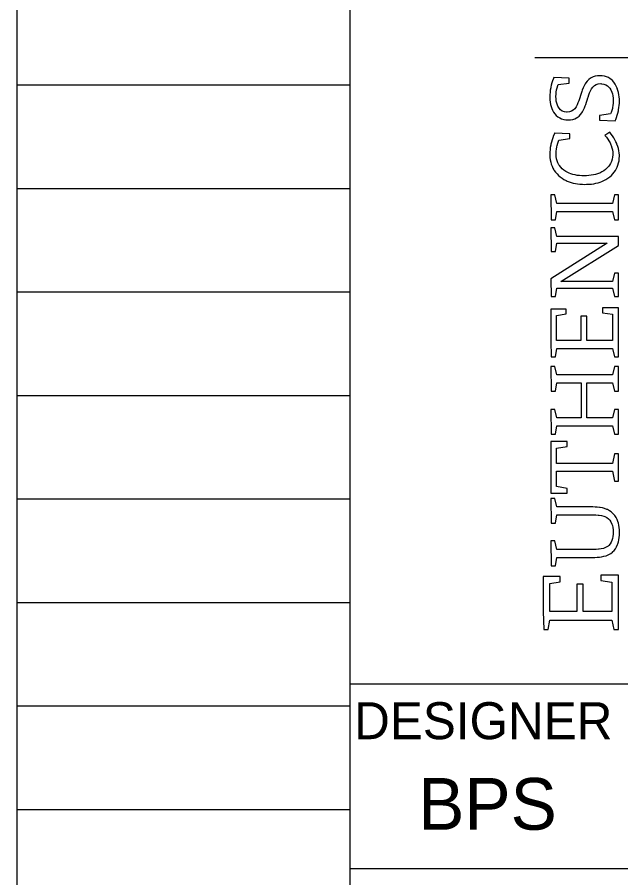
# Model space of a CAD drawing. Extents: x 0 to 34, y 0 to 22.
# Drawn here: x 31.1 to 32.732, y 2.475 to 4.803 of the extents above; entities that cross this region are included whole.
import ezdxf

# ---------------------------------------------------------------- set-up
doc = ezdxf.new("R2010")
doc.units = 0
for name, color, linetype in [('SH_Border', 7, 'Continuous'), ('SH_Data', 7, 'Continuous'), ('SH_Logo', 7, 'Continuous')]:
    doc.layers.add(name, color=color, linetype=linetype)

msp = doc.modelspace()

# ---------------------------------------------------------------- linework, layer by layer
at = {"layer": 'SH_Border'}
for p, q in [((32, 0.5), (32, 21.5)), ((32, 3), (33.5, 3)), ((32, 2.5), (33.5, 2.5))]:
    msp.add_line(p, q, dxfattribs=at)
at = {"layer": 'SH_Data'}
for p, q in [((31.1, 0.98), (31.1, 21.14)), ((32, 0.98), (32, 21.14)), ((31.1, 4.62), (32, 4.62)), ((31.1, 4.34), (32, 4.34)), ((31.1, 4.06), (32, 4.06)), ((31.1, 3.78), (32, 3.78)), ((31.1, 3.5), (32, 3.5)), ((31.1, 3.22), (32, 3.22)), ((31.1, 2.94), (32, 2.94)), ((31.1, 2.66), (32, 2.66))]:
    msp.add_line(p, q, dxfattribs=at)
at = {"layer": 'SH_Logo'}
msp.add_line((32.4993, 4.6945), (32.8389, 4.6945), dxfattribs=at)
for points in [[(32.6075, 4.5559), (32.6035, 4.5518), (32.5991, 4.549), (32.5936, 4.5472), (32.5862, 4.5465), (32.5794, 4.5474), (32.5739, 4.5495), (32.5692, 4.5527), (32.5651, 4.5572), (32.562, 4.5623), (32.5596, 4.5681), (32.5589, 4.5705), (32.5577, 4.5764), (32.5569, 4.5824), (32.5567, 4.5887), (32.5569, 4.5949), (32.5575, 4.6009), (32.5585, 4.607), (32.5599, 4.6127), (32.5616, 4.6186), (32.5627, 4.6212), (32.5922, 4.6249), (32.5922, 4.638), (32.5509, 4.6402), (32.5497, 4.6372), (32.5475, 4.6314), (32.5456, 4.6256), (32.5441, 4.6198), (32.5428, 4.6139), (32.5425, 4.6123), (32.5414, 4.606), (32.5407, 4.6), (32.5403, 4.5939), (32.5401, 4.5881), (32.5401, 4.5859), (32.5405, 4.5795), (32.5412, 4.5734), (32.5423, 4.5674), (32.5437, 4.5617), (32.5456, 4.5563), (32.5474, 4.5521), (32.5504, 4.5467), (32.5539, 4.5417), (32.5577, 4.5375), (32.5622, 4.5338), (32.5668, 4.5307), (32.572, 4.5284), (32.5777, 4.5267), (32.5838, 4.5256), (32.5903, 4.5253), (32.5962, 4.5256), (32.6023, 4.5266), (32.6078, 4.5284), (32.6127, 4.5308), (32.6145, 4.5319), (32.6193, 4.5356), (32.6235, 4.5399), (32.6271, 4.5448), (32.6286, 4.5472), (32.6314, 4.5525), (32.634, 4.5581), (32.6361, 4.5639), (32.6373, 4.5675), (32.6393, 4.5734), (32.6411, 4.5791), (32.6429, 4.585), (32.6436, 4.5873), (32.6457, 4.5932), (32.6479, 4.5988), (32.6503, 4.6041), (32.6531, 4.6093), (32.6567, 4.6142), (32.6608, 4.6183), (32.6609, 4.6184), (32.6657, 4.6213), (32.6713, 4.623), (32.6779, 4.6236), (32.6802, 4.6235), (32.6864, 4.6225), (32.6918, 4.6205), (32.6965, 4.6173), (32.6981, 4.6158), (32.7021, 4.6115), (32.7053, 4.6065), (32.7078, 4.6007), (32.7093, 4.5963), (32.7107, 4.5905), (32.7115, 4.5844), (32.7118, 4.5775), (32.7115, 4.5709), (32.7108, 4.5648), (32.7097, 4.5587), (32.7093, 4.5568), (32.7077, 4.5509), (32.7057, 4.5451), (32.7043, 4.5417), (32.6742, 4.5376), (32.6742, 4.5248), (32.7173, 4.5232), (32.7187, 4.5266), (32.7208, 4.5324), (32.7226, 4.5382), (32.7242, 4.5441), (32.7255, 4.55), (32.726, 4.5527), (32.7271, 4.5588), (32.7277, 4.5648), (32.7282, 4.5708), (32.7283, 4.5768), (32.7283, 4.5812), (32.7278, 4.5875), (32.7271, 4.5936), (32.7259, 4.5994), (32.7244, 4.6052), (32.7223, 4.6114), (32.7199, 4.6171), (32.7169, 4.6224), (32.7135, 4.6273), (32.7096, 4.6317), (32.7052, 4.6357), (32.7036, 4.6369), (32.6988, 4.6398), (32.6935, 4.642), (32.6878, 4.6436), (32.6816, 4.6446), (32.675, 4.6449), (32.6688, 4.6446), (32.6626, 4.6436), (32.6571, 4.6419), (32.6521, 4.6396), (32.6501, 4.6383), (32.6453, 4.6345), (32.641, 4.6303), (32.6374, 4.6254), (32.6358, 4.6228), (32.6329, 4.6176), (32.6303, 4.612), (32.628, 4.6063), (32.6267, 4.6026), (32.6229, 4.5911), (32.6211, 4.5852), (32.6184, 4.577), (32.6161, 4.5714), (32.6137, 4.5661), (32.611, 4.5608)], [(32.6742, 4.5376), (32.6742, 4.5248), (32.7173, 4.5232), (32.7187, 4.5266), (32.7208, 4.5324), (32.7226, 4.5382), (32.7242, 4.5441), (32.7255, 4.55), (32.726, 4.5527), (32.7271, 4.5588), (32.7277, 4.5648), (32.7282, 4.5708), (32.7283, 4.5768), (32.7283, 4.5812), (32.7278, 4.5875), (32.7271, 4.5936), (32.7259, 4.5994), (32.7244, 4.6052), (32.7226, 4.6107), (32.7223, 4.6114), (32.7199, 4.6171), (32.7169, 4.6224), (32.7135, 4.6273), (32.7096, 4.6317), (32.7052, 4.6357), (32.7036, 4.6369), (32.6988, 4.6398), (32.6935, 4.642), (32.6878, 4.6436), (32.6816, 4.6446), (32.675, 4.6449), (32.6688, 4.6446), (32.6626, 4.6436), (32.6571, 4.6419), (32.6521, 4.6396), (32.6501, 4.6383), (32.6453, 4.6345), (32.641, 4.6303), (32.6374, 4.6254), (32.6358, 4.6228), (32.6329, 4.6176), (32.6303, 4.612), (32.628, 4.6063), (32.6267, 4.6026), (32.6248, 4.5968), (32.6229, 4.5911), (32.6211, 4.5852), (32.6204, 4.5829), (32.6184, 4.577), (32.6161, 4.5714), (32.6137, 4.5661), (32.611, 4.5608), (32.6075, 4.5559), (32.6035, 4.5518), (32.5991, 4.549), (32.5936, 4.5472), (32.5871, 4.5466), (32.5856, 4.5466), (32.5794, 4.5474), (32.5739, 4.5495), (32.5693, 4.5526), (32.569, 4.5529), (32.5651, 4.5572), (32.562, 4.5623), (32.5596, 4.5681), (32.5589, 4.5705), (32.5577, 4.5764), (32.5569, 4.5824), (32.5567, 4.5886), (32.5567, 4.5889), (32.5569, 4.5949), (32.5575, 4.6009), (32.5585, 4.607), (32.5599, 4.6127), (32.5616, 4.6186), (32.5627, 4.6212), (32.5922, 4.6249), (32.5922, 4.638), (32.5509, 4.6402), (32.5497, 4.6372), (32.5475, 4.6314), (32.5456, 4.6256), (32.5441, 4.6198), (32.5428, 4.6139), (32.5425, 4.6123), (32.5414, 4.606), (32.5407, 4.6), (32.5403, 4.5939), (32.5401, 4.5881), (32.5401, 4.5859), (32.5405, 4.5795), (32.5412, 4.5734), (32.5423, 4.5674), (32.5437, 4.5617), (32.5456, 4.5563), (32.5474, 4.5521), (32.5504, 4.5467), (32.5539, 4.5417), (32.5577, 4.5375), (32.5622, 4.5338), (32.5668, 4.5307), (32.572, 4.5284), (32.5777, 4.5267), (32.5838, 4.5256), (32.5903, 4.5253), (32.5962, 4.5256), (32.6023, 4.5266), (32.6078, 4.5284), (32.6127, 4.5308), (32.6145, 4.5319), (32.6193, 4.5356), (32.6235, 4.5399), (32.6271, 4.5448), (32.6286, 4.5472), (32.6314, 4.5525), (32.634, 4.5581), (32.6361, 4.5639), (32.6373, 4.5675), (32.6393, 4.5734), (32.6411, 4.5791), (32.6429, 4.585), (32.6436, 4.5873), (32.6457, 4.5932), (32.6479, 4.5988), (32.6503, 4.6041), (32.6531, 4.6093), (32.6567, 4.6142), (32.6608, 4.6183), (32.6609, 4.6184), (32.6657, 4.6213), (32.6713, 4.623), (32.6779, 4.6236), (32.6802, 4.6235), (32.6864, 4.6225), (32.6918, 4.6205), (32.6965, 4.6173), (32.6981, 4.6158), (32.7021, 4.6115), (32.7053, 4.6065), (32.7078, 4.6007), (32.7093, 4.5963), (32.7107, 4.5905), (32.7115, 4.5844), (32.7118, 4.5781), (32.7118, 4.5768), (32.7115, 4.5709), (32.7108, 4.5648), (32.7097, 4.5587), (32.7093, 4.5568), (32.7077, 4.5509), (32.7057, 4.5451), (32.7043, 4.5417)], [(32.5558, 4.3837), (32.5596, 4.3793), (32.5637, 4.3751), (32.5682, 4.3712), (32.5731, 4.3676), (32.5784, 4.3644), (32.584, 4.3614), (32.5873, 4.3599), (32.5925, 4.3578), (32.5979, 4.3561), (32.6035, 4.3546), (32.6093, 4.3533), (32.6154, 4.3523), (32.6217, 4.3517), (32.6283, 4.3513), (32.635, 4.3511), (32.6396, 4.3512), (32.6463, 4.3515), (32.6527, 4.3521), (32.6589, 4.353), (32.6648, 4.3541), (32.6705, 4.3555), (32.6759, 4.3572), (32.6811, 4.3591), (32.686, 4.3614), (32.6861, 4.3614), (32.6918, 4.3644), (32.6971, 4.3677), (32.7021, 4.3713), (32.7065, 4.3752), (32.7106, 4.3794), (32.7143, 4.3839), (32.7176, 4.3887), (32.7197, 4.3923), (32.7223, 4.3977), (32.7245, 4.4033), (32.7261, 4.409), (32.7274, 4.4148), (32.7281, 4.4208), (32.7283, 4.4271), (32.7283, 4.4302), (32.7278, 4.436), (32.727, 4.442), (32.7257, 4.4479), (32.7239, 4.4539), (32.7218, 4.4599), (32.7212, 4.4613), (32.7189, 4.4666), (32.7163, 4.4719), (32.7133, 4.4771), (32.7099, 4.4822), (32.7062, 4.4872), (32.7021, 4.4922), (32.6892, 4.4835), (32.6932, 4.4787), (32.6969, 4.4736), (32.7001, 4.4685), (32.7029, 4.4633), (32.7052, 4.4581), (32.7059, 4.4562), (32.7079, 4.45), (32.7093, 4.4441), (32.7102, 4.4382), (32.7105, 4.4326), (32.7104, 4.431), (32.71, 4.4249), (32.7088, 4.419), (32.7069, 4.4134), (32.7044, 4.408), (32.7013, 4.4029), (32.6991, 4.3998), (32.6953, 4.3955), (32.691, 4.3916), (32.6862, 4.388), (32.6808, 4.3847), (32.675, 4.3818), (32.6741, 4.3815), (32.6691, 4.3796), (32.6637, 4.378), (32.658, 4.3766), (32.6521, 4.3756), (32.6458, 4.3748), (32.6393, 4.3744), (32.6324, 4.3742), (32.627, 4.3743), (32.6205, 4.3748), (32.6143, 4.3755), (32.6083, 4.3765), (32.6026, 4.3779), (32.5972, 4.3796), (32.5922, 4.3816), (32.589, 4.3831), (32.5834, 4.386), (32.5783, 4.3894), (32.5738, 4.3932), (32.5697, 4.3973), (32.5662, 4.4018), (32.5646, 4.4042), (32.562, 4.4093), (32.5599, 4.4147), (32.5584, 4.4205), (32.5575, 4.4267), (32.5572, 4.4331), (32.5572, 4.4347), (32.5575, 4.4406), (32.5582, 4.4467), (32.5593, 4.453), (32.5602, 4.4567), (32.5618, 4.4625), (32.5638, 4.4682), (32.5647, 4.4705), (32.5945, 4.4749), (32.5945, 4.4878), (32.5532, 4.4896), (32.553, 4.489), (32.5505, 4.4831), (32.5482, 4.4772), (32.5463, 4.4714), (32.5447, 4.4657), (32.5433, 4.4602), (32.5426, 4.4569), (32.5415, 4.4508), (32.5407, 4.4447), (32.5403, 4.4387), (32.5401, 4.4328), (32.5402, 4.4299), (32.5406, 4.4236), (32.5413, 4.4175), (32.5425, 4.4116), (32.5441, 4.4059), (32.5462, 4.4003), (32.5486, 4.3951), (32.5514, 4.39), (32.5523, 4.3885)], [(32.6205, 4.3748), (32.6143, 4.3755), (32.6083, 4.3765), (32.6026, 4.3779), (32.5972, 4.3796), (32.5922, 4.3816), (32.589, 4.3831), (32.5834, 4.386), (32.5783, 4.3894), (32.5738, 4.3932), (32.5697, 4.3973), (32.5662, 4.4018), (32.5646, 4.4042), (32.562, 4.4093), (32.5599, 4.4147), (32.5584, 4.4205), (32.5575, 4.4267), (32.5572, 4.4331), (32.5572, 4.4347), (32.5575, 4.4406), (32.5582, 4.4467), (32.5593, 4.453), (32.5602, 4.4567), (32.5618, 4.4625), (32.5638, 4.4682), (32.5647, 4.4705), (32.5945, 4.4749), (32.5945, 4.4878), (32.5533, 4.4896), (32.5505, 4.4831), (32.5482, 4.4772), (32.5463, 4.4714), (32.5447, 4.4657), (32.5433, 4.4602), (32.5426, 4.4569), (32.5415, 4.4508), (32.5407, 4.4447), (32.5403, 4.4387), (32.5401, 4.4328), (32.5402, 4.4299), (32.5406, 4.4236), (32.5413, 4.4175), (32.5425, 4.4116), (32.5441, 4.4059), (32.5462, 4.4003), (32.5486, 4.3951), (32.5514, 4.39), (32.5523, 4.3885), (32.5558, 4.3837), (32.5596, 4.3793), (32.5637, 4.3751), (32.5682, 4.3712), (32.5731, 4.3676), (32.5784, 4.3644), (32.584, 4.3614), (32.5873, 4.3599), (32.5925, 4.3578), (32.5979, 4.3561), (32.6035, 4.3546), (32.6093, 4.3533), (32.6154, 4.3523), (32.6217, 4.3517), (32.6283, 4.3513), (32.635, 4.3511), (32.6396, 4.3512), (32.6463, 4.3515), (32.6527, 4.3521), (32.6589, 4.353), (32.6648, 4.3541), (32.6705, 4.3555), (32.6759, 4.3572), (32.6811, 4.3591), (32.6866, 4.3617), (32.6918, 4.3644), (32.6971, 4.3677), (32.7021, 4.3713), (32.7065, 4.3752), (32.7106, 4.3794), (32.7143, 4.3839), (32.7176, 4.3887), (32.7197, 4.3923), (32.7223, 4.3977), (32.7245, 4.4033), (32.7261, 4.409), (32.7274, 4.4148), (32.7281, 4.4208), (32.7283, 4.4271), (32.7283, 4.4302), (32.7278, 4.436), (32.727, 4.442), (32.7257, 4.4479), (32.7239, 4.4539), (32.7218, 4.4599), (32.7212, 4.4613), (32.7189, 4.4666), (32.7163, 4.4719), (32.7133, 4.4771), (32.7099, 4.4822), (32.7062, 4.4872), (32.7021, 4.4922), (32.6892, 4.4835), (32.6932, 4.4787), (32.6969, 4.4736), (32.7001, 4.4685), (32.7029, 4.4633), (32.7052, 4.4581), (32.7059, 4.4562), (32.7079, 4.45), (32.7093, 4.4441), (32.7102, 4.4382), (32.7105, 4.4326), (32.7104, 4.431), (32.71, 4.4249), (32.7088, 4.419), (32.7069, 4.4134), (32.7044, 4.408), (32.7013, 4.4029), (32.6991, 4.3998), (32.6953, 4.3955), (32.691, 4.3916), (32.6862, 4.388), (32.6808, 4.3847), (32.6747, 4.3817), (32.6691, 4.3796), (32.6637, 4.378), (32.658, 4.3766), (32.6521, 4.3756), (32.6458, 4.3748), (32.6393, 4.3744), (32.6324, 4.3742), (32.627, 4.3743)], [(32.5425, 4.3225), (32.5438, 4.2554), (32.5551, 4.2554), (32.5592, 4.2781), (32.71, 4.2781), (32.7147, 4.2554), (32.726, 4.2554), (32.726, 4.3225), (32.7147, 4.3225), (32.71, 4.2996), (32.5589, 4.2996), (32.5538, 4.3225)], [(32.5589, 4.2996), (32.5538, 4.3225), (32.5425, 4.3225), (32.5438, 4.2554), (32.5551, 4.2554), (32.5592, 4.2781), (32.71, 4.2781), (32.7147, 4.2554), (32.726, 4.2554), (32.726, 4.3225), (32.7147, 4.3225), (32.71, 4.2996)], [(32.5591, 4.07), (32.71, 4.07), (32.7147, 4.0474), (32.726, 4.0474), (32.726, 4.111), (32.7147, 4.111), (32.71, 4.0884), (32.5703, 4.0884), (32.726, 4.1861), (32.726, 4.2103), (32.559, 4.2103), (32.5538, 4.2332), (32.5425, 4.2332), (32.5438, 4.1693), (32.5551, 4.1693), (32.5589, 4.1921), (32.6954, 4.1921), (32.5425, 4.0958), (32.5438, 4.0474), (32.5551, 4.0474)], [(32.5703, 4.0884), (32.726, 4.1861), (32.726, 4.2103), (32.559, 4.2103), (32.5538, 4.2332), (32.5425, 4.2332), (32.5438, 4.1693), (32.5551, 4.1693), (32.5589, 4.1921), (32.6954, 4.1921), (32.5425, 4.0958), (32.5438, 4.0474), (32.5551, 4.0474), (32.5591, 4.07), (32.71, 4.07), (32.7147, 4.0474), (32.726, 4.0474), (32.726, 4.111), (32.7147, 4.111), (32.71, 4.0884)], [(32.6829, 4.0169), (32.6829, 4.0038), (32.71, 3.9996), (32.71, 3.9283), (32.64, 3.9283), (32.64, 3.9946), (32.6242, 3.9946), (32.6242, 3.9283), (32.5585, 3.9283), (32.5585, 3.9964), (32.584, 4.0006), (32.584, 4.0138), (32.5425, 4.0138), (32.5425, 3.9281), (32.5438, 3.8843), (32.5551, 3.8843), (32.5592, 3.9068), (32.7099, 3.9068), (32.7147, 3.8843), (32.726, 3.8843), (32.726, 4.0169)], [(32.6242, 3.9946), (32.6242, 3.9283), (32.5585, 3.9283), (32.5585, 3.9964), (32.584, 4.0006), (32.584, 4.0138), (32.5425, 4.0138), (32.5425, 3.9281), (32.5438, 3.8843), (32.5551, 3.8843), (32.5592, 3.9068), (32.7099, 3.9068), (32.7147, 3.8843), (32.726, 3.8843), (32.726, 4.0169), (32.6829, 4.0169), (32.6829, 4.0038), (32.71, 3.9996), (32.71, 3.9283), (32.64, 3.9283), (32.64, 3.9946)], [(32.5425, 3.8587), (32.5438, 3.7918), (32.5551, 3.7918), (32.5591, 3.8143), (32.6245, 3.8143), (32.6245, 3.7193), (32.559, 3.7193), (32.5538, 3.7421), (32.5425, 3.7421), (32.5438, 3.6751), (32.5551, 3.6751), (32.5591, 3.6977), (32.7099, 3.6977), (32.7147, 3.6751), (32.726, 3.6751), (32.726, 3.7421), (32.7147, 3.7421), (32.7099, 3.7193), (32.6406, 3.7193), (32.6406, 3.8143), (32.7099, 3.8143), (32.7147, 3.7918), (32.726, 3.7918), (32.726, 3.8587), (32.7147, 3.8587), (32.7099, 3.8359), (32.559, 3.8359), (32.5538, 3.8587)], [(32.559, 3.8359), (32.5538, 3.8587), (32.5425, 3.8587), (32.5438, 3.7918), (32.5551, 3.7918), (32.5591, 3.8143), (32.6245, 3.8143), (32.6245, 3.7193), (32.559, 3.7193), (32.5538, 3.7421), (32.5425, 3.7421), (32.5438, 3.6751), (32.5551, 3.6751), (32.5591, 3.6977), (32.7099, 3.6977), (32.7147, 3.6751), (32.726, 3.6751), (32.726, 3.7421), (32.7147, 3.7421), (32.7099, 3.7193), (32.6406, 3.7193), (32.6406, 3.8143), (32.7099, 3.8143), (32.7147, 3.7918), (32.726, 3.7918), (32.726, 3.8587), (32.7147, 3.8587), (32.7099, 3.8359)], [(32.5585, 3.596), (32.5585, 3.6373), (32.5874, 3.642), (32.5874, 3.6551), (32.5425, 3.6551), (32.5425, 3.5156), (32.5874, 3.5156), (32.5874, 3.5287), (32.5585, 3.5333), (32.5585, 3.5747), (32.7099, 3.5747), (32.7147, 3.5484), (32.726, 3.5484), (32.726, 3.6223), (32.7147, 3.6223), (32.7099, 3.596)], [(32.5585, 3.596), (32.5585, 3.6373), (32.5874, 3.642), (32.5874, 3.6551), (32.5425, 3.6551), (32.5425, 3.5156), (32.5874, 3.5156), (32.5874, 3.5287), (32.5585, 3.5333), (32.5585, 3.5747), (32.7099, 3.5747), (32.7147, 3.5484), (32.726, 3.5484), (32.726, 3.6223), (32.7147, 3.6223), (32.7099, 3.596)], [(32.7116, 3.4095), (32.7114, 3.4048), (32.7108, 3.3983), (32.7097, 3.3926), (32.7081, 3.3877), (32.7063, 3.3834), (32.7032, 3.3782), (32.6994, 3.374), (32.6979, 3.3726), (32.6929, 3.3692), (32.6873, 3.3669), (32.6851, 3.3662), (32.6793, 3.3648), (32.6732, 3.3641), (32.6717, 3.3639), (32.6654, 3.3636), (32.6595, 3.3635), (32.5589, 3.3635), (32.5538, 3.3863), (32.5425, 3.3863), (32.5438, 3.3194), (32.5551, 3.3194), (32.559, 3.3419), (32.6595, 3.3419), (32.6619, 3.342), (32.6678, 3.3422), (32.6745, 3.3428), (32.6803, 3.3435), (32.6862, 3.3448), (32.6923, 3.3464), (32.6944, 3.3471), (32.6998, 3.3495), (32.705, 3.3526), (32.71, 3.3564), (32.71, 3.3565), (32.714, 3.3604), (32.7176, 3.365), (32.7207, 3.3703), (32.7233, 3.3764), (32.7242, 3.3787), (32.7257, 3.3839), (32.7268, 3.3895), (32.7277, 3.3956), (32.7282, 3.4022), (32.7283, 3.4092), (32.7283, 3.4095), (32.7282, 3.4163), (32.7277, 3.4227), (32.7268, 3.4287), (32.7256, 3.4343), (32.7242, 3.4394), (32.7223, 3.4443), (32.7195, 3.4499), (32.7163, 3.4548), (32.7125, 3.4591), (32.7109, 3.4607), (32.7063, 3.4648), (32.7013, 3.4682), (32.696, 3.471), (32.6941, 3.4718), (32.6884, 3.4739), (32.6826, 3.4755), (32.6766, 3.4768), (32.6748, 3.477), (32.6686, 3.4777), (32.6625, 3.4781), (32.6566, 3.4783), (32.5589, 3.4783), (32.5538, 3.5012), (32.5425, 3.5012), (32.5438, 3.4342), (32.5551, 3.4342), (32.5589, 3.4568), (32.6566, 3.4568), (32.6588, 3.4568), (32.6649, 3.4566), (32.671, 3.4562), (32.6739, 3.456), (32.6799, 3.4549), (32.6858, 3.4534), (32.6886, 3.4523), (32.694, 3.4496), (32.6989, 3.446), (32.702, 3.4428), (32.7053, 3.4378), (32.7081, 3.4321), (32.7093, 3.4282), (32.7106, 3.4226), (32.7112, 3.4163)], [(32.5589, 3.3635), (32.5538, 3.3863), (32.5425, 3.3863), (32.5438, 3.3194), (32.5551, 3.3194), (32.559, 3.3419), (32.6595, 3.3419), (32.6619, 3.342), (32.6678, 3.3422), (32.6745, 3.3428), (32.6803, 3.3435), (32.6862, 3.3448), (32.6923, 3.3464), (32.6944, 3.3471), (32.6998, 3.3495), (32.705, 3.3526), (32.71, 3.3564), (32.714, 3.3604), (32.7176, 3.365), (32.7207, 3.3703), (32.7233, 3.3764), (32.7242, 3.3787), (32.7257, 3.3839), (32.7268, 3.3895), (32.7277, 3.3956), (32.7282, 3.4022), (32.7283, 3.4092), (32.7283, 3.4095), (32.7282, 3.4163), (32.7277, 3.4227), (32.7268, 3.4287), (32.7256, 3.4343), (32.7242, 3.4394), (32.7223, 3.4443), (32.7195, 3.4499), (32.7163, 3.4548), (32.7125, 3.4591), (32.7109, 3.4607), (32.7063, 3.4648), (32.7013, 3.4682), (32.696, 3.471), (32.6941, 3.4718), (32.6884, 3.4739), (32.6826, 3.4755), (32.6766, 3.4768), (32.6748, 3.477), (32.6686, 3.4777), (32.6625, 3.4781), (32.6566, 3.4783), (32.5589, 3.4783), (32.5538, 3.5012), (32.5425, 3.5012), (32.5438, 3.4342), (32.5551, 3.4342), (32.5589, 3.4568), (32.6588, 3.4568), (32.6649, 3.4566), (32.671, 3.4562), (32.6739, 3.456), (32.6799, 3.4549), (32.6858, 3.4534), (32.6886, 3.4523), (32.694, 3.4496), (32.6989, 3.446), (32.702, 3.4428), (32.7053, 3.4378), (32.7081, 3.4321), (32.7093, 3.4282), (32.7106, 3.4226), (32.7112, 3.4163), (32.7116, 3.4095), (32.7114, 3.4048), (32.7108, 3.3983), (32.7097, 3.3926), (32.7081, 3.3877), (32.7063, 3.3834), (32.7032, 3.3782), (32.6994, 3.374), (32.6979, 3.3726), (32.6929, 3.3692), (32.6873, 3.3669), (32.6851, 3.3662), (32.6793, 3.3648), (32.6722, 3.3639), (32.6654, 3.3636), (32.6595, 3.3635)], [(32.5361, 3.1467), (32.5406, 3.1718), (32.7081, 3.1718), (32.7134, 3.1467), (32.726, 3.1467), (32.726, 3.2941), (32.6781, 3.2941), (32.6781, 3.2795), (32.7082, 3.275), (32.7082, 3.1958), (32.6305, 3.1958), (32.6305, 3.2693), (32.6129, 3.2693), (32.6129, 3.1958), (32.5399, 3.1958), (32.5399, 3.2714), (32.5683, 3.2761), (32.5683, 3.2906), (32.5221, 3.2906), (32.5221, 3.1954), (32.5236, 3.1467)], [(32.5399, 3.1958), (32.5399, 3.2714), (32.5683, 3.2761), (32.5683, 3.2906), (32.5221, 3.2906), (32.5221, 3.1954), (32.5236, 3.1467), (32.5361, 3.1467), (32.5406, 3.1718), (32.7081, 3.1718), (32.7134, 3.1467), (32.726, 3.1467), (32.726, 3.2941), (32.6781, 3.2941), (32.6781, 3.2795), (32.7082, 3.275), (32.7082, 3.1958), (32.6305, 3.1958), (32.6305, 3.2693), (32.6129, 3.2693), (32.6129, 3.1958)]]:
    msp.add_lwpolyline(points, close=True, dxfattribs=at)
for points in [[(32.5585, 3.6373), (32.5874, 3.642), (32.5874, 3.6551), (32.5425, 3.6551)], [(32.5585, 3.5747), (32.7099, 3.5747), (32.7147, 3.5484), (32.726, 3.5484), (32.726, 3.6223), (32.7147, 3.6223), (32.7099, 3.596), (32.5585, 3.596)]]:
    msp.add_lwpolyline(points, dxfattribs=at)

# ---------------------------------------------------------------- texts
at = {"layer": 'SH_Data'}
for s, height, p in [('DESIGNER', 0.1, (32.011, 2.85)), ('BPS', 0.14, (32.1844, 2.605))]:
    msp.add_text(s, height=height, dxfattribs=at).set_placement(p)

doc.saveas('drawing.dxf')
